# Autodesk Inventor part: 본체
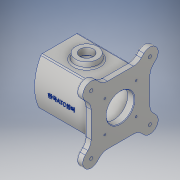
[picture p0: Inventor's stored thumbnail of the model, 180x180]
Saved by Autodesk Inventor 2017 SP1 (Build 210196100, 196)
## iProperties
Part Number: 본체
Material: 알루미늄 6061
Document SubType Name: Modeling
Designer: Administrator
Density: 2.7 g/cm^3
Appearance: 알루미늄 - 평지
Mass: 1224.57 g
Surface Area: 906.054 cm^2
Volume: 453.543 cm^3
Author: Administrator
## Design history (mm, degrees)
sketch "스케치1"
  geometry: L1 (-53, 53)-(53, 53); L2 (53, 53)-(53, -53); L3 (53, -53)-(-53, -53); L4 (-53, -53)-(-53, 53); L5 (-53, 53)-(53, -53); L6 (53, 53)-(-53, -53); L7 (-53.033, 53.033)-(53.033, -53.033); L8 (-63.64, 42.426)-(42.426, -63.64); L9 (63.64, -42.426)-(-42.426, 63.64); L10 (-53.033, -53.033)-(53.033, 53.033); L11 (-42.426, -63.64)-(63.64, 42.426); L12 (42.426, 63.64)-(-63.64, -42.426); C1 r 75 at (0, 0); C2 r 15 at (53, 53); C3 r 15 at (53, -53); C4 r 15 at (-53, 53); C5 r 15 at (-53, -53); A1 r 15 centre (-53.033, 53.033) between (-42.426, 63.64) and (-63.64, 42.426); A2 r 15 centre (53.033, -53.033) between (42.426, -63.64) and (63.64, -42.426); A3 r 15 centre (-53.033, -53.033) between (-63.64, -42.426) and (-42.426, -63.64); A4 r 15 centre (53.033, 53.033) between (63.64, 42.426) and (42.426, 63.64); 1 further point
  constraints: 28 end point, 9 centre point, 8 point on circle, 8 tangent, 5 coincident, 4 midpoint, 4 parallel, 2 collinear, 1 horizontal, 1 perpendicular
  dimensions: "d0" = 150 diameter of C1; "d1" = 106 distance of L2.end L3.end; "d2" = 106 distance of L1.end L2.end; "d3" = 30 diameter of C2; "d4" = 30 diameter of C3; "d5" = 30 diameter of C4; "d6" = 30 diameter of C5; "d126" = 15 radius of A2; "d127" = 150 distance of L7.start L7.end; "d128" = 15 radius of A4; "d129" = 150 distance of L10.start L10.end
extrude "돌출1" new body sketch "스케치1" distance "d7" = 12; taper "d8" = 0 deg
sketch "스케치2"
  geometry: L1 (-45, -45)-(45, -45); L2 (45, -45)-(45, 45); L3 (45, 45)-(-45, 45); L4 (-45, 45)-(-45, -45); L5 (-45, -45)-(45, 45); L6 (45, -45)-(-45, 45); L7 (-45, 0)-(45, 0); L8 (0, 45)-(0, -45); L9 (-32.942, 45)-(32.942, 45); A1 r 90 centre (45, 0) between (-32.942, 45) and (-37.029, -37.029); A2 r 90 centre (-45, 0) between (37.029, -37.029) and (32.942, 45); A3 r 90 centre (0, 45) between (-37.029, -37.029) and (37.029, -37.029); 2 further points
  constraints: 18 end point, 9 point on circle, 5 midpoint, 3 centre point, 3 tangent, 2 parallel, 2 point on line, 1 coincident, 1 collinear, 1 horizontal, 1 perpendicular
  dimensions: "d10" = 90 distance of L2.end L1.end; "d11" = 90 distance of L2.end L3.end; "d107" = 90 radius of A2; "d108" = 90 radius of A1; "d109" = 90 radius of A3
extrude "돌출2" join sketch "스케치2" distance "d12" = 98; taper "d13" = 0 deg
sketch "스케치3"
  geometry: L1 (-45, 45)-(45, 45) reference; L2 (0, 0)-(-28.284, -28.284); L3 (0, -40)-(0, 40); L4 (40, 0)-(-40, 0); L5 (0, 40)-(0, -40); L6 (-40, 0)-(40, 0); A1 r 40 centre (0, 0) between (-28.284, -28.284) and (0, -40); 8 further points
  constraints: 10 end point, 3 coincident, 3 point on circle, 1 centre point, 1 midpoint, 1 vertical, 19 other
  dimensions: "d14" = 80 diameter of A1; "d16" = 45 deg angle of L2 L3; "d19" = 360 deg dimension on L2.start L3.start (derived)
hole "구멍1" sketch "스케치3" at (-28.284, -28.284), (28.284, -28.284), (28.284, 28.284), (-28.284, 28.284) diameter "d21" = 3.242; stored, may be unused: countersink angle "d25" = 90 deg, drill point angle "d27" = 118 deg; dims "d22" = 9, "d23" = 4, "d24" = 2, "d26" = 11
sketch "스케치5"
  geometry: L1 (-45, -45)-(45, -45) reference; L2 (45, 45)-(-45, 45) reference; L3 (-45, -45)-(-45, 45) reference; L4 (45, -45)-(45, 45) reference; L5 (-45, 45)-(45, 45) reference; L6 (-45, -45)-(-45, 45); L7 (45, -45)-(-45, -45) reference; L8 (-45, -45)-(45, -45); L9 (45, 45)-(45, -45) reference; L10 (45, -45)-(45, 45); L11 (-45, 45)-(-45, -45) reference; A1 r 180 centre (0.645, 135) between (-39.941, -40.365) and (45, -39.45); A2 r 180 centre (135, 2.012) between (-39.791, 45) and (-39.941, -40.365); A3 r 180 centre (-135, -2.173) between (39.831, -45) and (38.709, 45); 1 further point
  constraints: 6 end point, 6 point on circle, 4 point on line, 3 centre point, 3 tangent, 2 collinear, 1 vertical
  dimensions: "d104" = 180 radius of A1; "d105" = 180 radius of A3; "d106" = 180 radius of A2
extrude "돌출3" join sketch "스케치5" stored distance "d35" = 110; taper "d36" = 0 deg
sketch "스케치6"
  geometry: L1 (-110, 0)-(0, 0); L2 (-110, 0)-(-110, 25); L3 (-110, 25)-(-98, 25); L4 (-98, 25)-(-98, 37); L5 (-98, 37)-(-12, 37); L6 (-12, 37)-(-12, 25); L7 (-12, 25)-(0, 25); L8 (0, 25)-(0, 0); L9 (0, 31.787)-(0, -31.787) reference; 3 further points
  constraints: 16 end point, 3 perpendicular, 2 horizontal, 1 collinear, 1 midpoint, 1 vertical
  dimensions: "d37" = 50 diameter of L3 L1; "d38" = 74 diameter of L5 L1; "d39" = 50 diameter of L7 L1; "d41" = 12 distance between parallel lines of L9 L6; "d42" = 86 distance of L4.end L5.end (derived)
revolve "회전1" sketch "스케치6" stored, may be unused: angle "d43" = 90 deg
node "작업 평면1"
sketch "스케치8"
  geometry: L1 (0, 31.787)-(0, -31.787) reference; C1 r 20 at (61, 0); C2 r 12 at (61, 0); 3 further points
  constraints: 2 centre point, 1 coincident, 1 horizontal alignment
  dimensions: "d48" = 40 diameter of C1; "d49" = 24 diameter of C2; "d50" = 61 distance from line of C1.centre L1
extrude "돌출4" join sketch "스케치8" stored distance "d51" = 110; taper "d52" = 10 deg
node "작업 평면2"
sketch "스케치14"
  geometry: C1 r 12 at (0, 0); 1 further point
  constraints: 1 centre point
  dimensions: "d97" = 24 diameter of C1
extrude "돌출7" cut sketch "스케치14" distance "d98" = 13; taper "d99" = 0 deg
sketch "스케치10"
  geometry: C1 r 15 at (0, 0); 2 further points
  constraints: 1 centre point, 1 coincident
  dimensions: "d55" = 30 diameter of C1
extrude "돌출6" cut sketch "스케치10" distance "d56" = 20; taper "d57" = 0 deg
sketch "스케치13"
  geometry: L1 (-53, 53)-(0, 0); L2 (-53, -53)-(0, 0); L3 (53, -53)-(0, 0); L4 (53, 53)-(0, 0); C1 r 40 at (0, 0); C2 r 1.621 at (-28.284, 28.284) reference; 5 further points
  constraints: 8 end point, 4 coincident, 1 centre point, 15 other
  dimensions: "d77" = 80 diameter of C1; "d80" = 360 deg dimension on L1.end L1.start (derived)
hole "구멍4" sketch "스케치13" at (-28.284, 28.284), (-28.284, -28.284), (28.284, -28.284), (28.284, 28.284) diameter "d82" = 3.242; stored, may be unused: countersink angle "d86" = 90 deg, drill point angle "d88" = 118 deg; dims "d83" = 9, "d84" = 18, "d85" = 2, "d87" = 11
chamfer "모따기1" distance "d93" = 1; stored, may be unused: second distance "d94" = 2, angle "d95" = 45 deg
chamfer "모따기2" distance "d100" = 1; stored, may be unused: second distance "d101" = 2, angle "d102" = 45 deg
fillet "모깎기5" dims "d103" = 3
fillet "모깎기6" dims "d110" = 3
fillet "모깎기7" dims "d111" = 3
node "작업 평면3"
sketch "스케치15"
  geometry: L1 (-81, 55)-(-41, 55) reference; L2 (0, -31.787)-(0, 31.787) reference; 2 further points
  constraints: 1 other
  dimensions: "d113" = 55 distance from line of point (-61, 0) L1; "d130" = 61 distance from line of L2 point (-61, 0)
feature "엠보싱1" sketch "스케치15" dims "d0" = 150, "d1" = 106, "d2" = 106, "d3" = 30, "d4" = 30, "d5" = 30, "d6" = 30, "d115" = 1, "d116" = 0, "d126" = 15, "d127" = 150, "d128" = 15, "d129" = 150
sketch "스케치16"
  geometry: L1 (0, 0)-(-53.033, 53.033); L2 (0, 0)-(0, 75); L3 (0, 0)-(-75, 0); L4 (0, 0)-(0, -75); L5 (0, 0)-(75, 0); C1 r 26 at (0, 0) reference; A1 r 75 centre (0, 0) between (-53.033, 53.033) and (0, 75); 5 further points
  constraints: 10 end point, 2 coincident, 2 point on circle, 1 centre point, 1 vertical, 17 other
  dimensions: "d131" = 150 diameter of A1; "d132" = 45 deg angle of L1 L2; "d135" = 360 deg dimension on A1.centre L2.end (derived)
hole "구멍5" sketch "스케치16" at (-53.033, 53.033), (-53.033, -53.033), (53.033, -53.033), (53.033, 53.033) diameter "d137" = 9; stored, may be unused: countersink angle "d141" = 90 deg, drill point angle "d143" = 118 deg; dims "d138" = 9, "d139" = 18, "d140" = 2, "d142" = 11
fillet "모깎기8" dims "d144" = 20
fillet "모깎기9" dims "d145" = 3
node "솔리드1"
other parameters: "d47" = 55, "d112" = 55
